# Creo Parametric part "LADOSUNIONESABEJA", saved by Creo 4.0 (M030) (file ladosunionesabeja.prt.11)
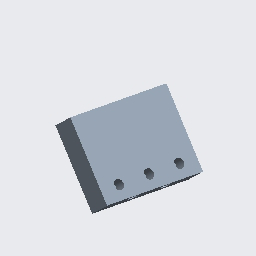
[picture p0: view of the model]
Units: millimeter Newton Second (mmNs); MM, TONNE, SECS

Created from: MMNS_PART_SOLID.PRT

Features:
  1. datum plane "RIGHT"
  2. datum plane "TOP"
  3. datum plane "FRONT"
  4. coordinate system
  5. sketch "Sketch 1"
  6. extrusion "Extrude 1"
  7. pattern "Pattern 1"
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
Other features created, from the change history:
  hole "Hole 1"
  hole "Hole 1 [2]"
  hole "Hole 1 [3]"
  hole "Hole 2"
  pattern "Patrón 2"
  hole "Taladro 2 [2]"
  hole "Hole 3"
  pattern "Pattern 3"
  hole "Hole 3 [2]"

Surfaces: 11 plane, 5 cylinder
